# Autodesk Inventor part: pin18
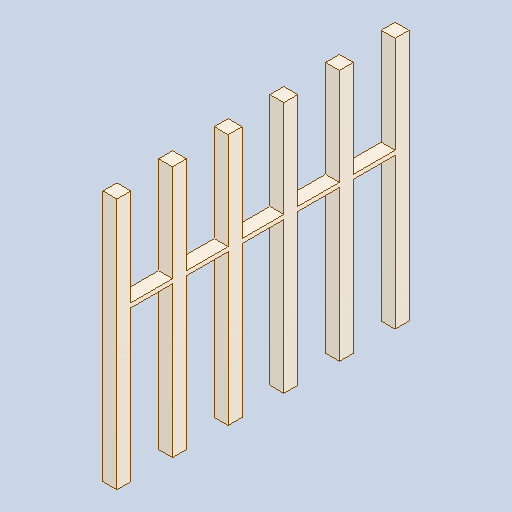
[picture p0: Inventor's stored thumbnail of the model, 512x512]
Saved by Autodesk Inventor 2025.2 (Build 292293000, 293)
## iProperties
Created: 2025-04
Part Number: pin18
Material: Generic
Description: PART--DESC
Document SubType Name: Modeling
Designer: BennF
Density: 1 g/cm^3
Appearance: Default
Author: BennF
Revision Number: NONE
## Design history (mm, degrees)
feature "Solid1"
body "Solid2"
